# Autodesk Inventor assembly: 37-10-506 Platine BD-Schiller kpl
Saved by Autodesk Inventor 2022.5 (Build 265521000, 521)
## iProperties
Created: 2024-12
Part Number: 37-10-506 Platine BD-Schiller kpl
Document SubType Name: Assembly
Designer: AdminForWorker
Title: 37-10-506 Platine BD-Schiller kpl v1
Author: AdminForWorker
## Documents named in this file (4)
- c:\worker\convert-fusion-r05-cosv3\tmp\job-1\137\temp\files\71a56e1c-7209-48b3-b2cf-f79746e6226c\06bbf12f-f1bb-4239-99a2-3d25c5ee1338.zip.iam
- c:\worker\convert-fusion-r05-cosv3\tmp\job-1\137\temp\files\71a56e1c-7209-48b3-b2cf-f79746e6226c\37-10-504-CH Platine BD (Schiller), teilbestückt.ipt
- c:\worker\convert-fusion-r05-cosv3\tmp\job-1\137\temp\files\71a56e1c-7209-48b3-b2cf-f79746e6226c\Präzisionsbuchsenleiste 16-polig (69-01-049).iam
- c:\worker\convert-fusion-r05-cosv3\tmp\job-1\137\temp\files\71a56e1c-7209-48b3-b2cf-f79746e6226c\Lötkelchleiste SIL3x1 2,54mm 90° (69-01-057).ipt
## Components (4 placed, 3 different names)
1. 37-10-504-CH Platine BD (Schiller), teilbestückt:1
2. Präzisionsbuchsenleiste 16-polig (69-01-049):1 [sub-assembly]
3. Präzisionsbuchsenleiste 16-polig (69-01-049):2 [sub-assembly]
4. Lötkelchleiste SIL3x1 2,54mm 90° (69-01-057):1
